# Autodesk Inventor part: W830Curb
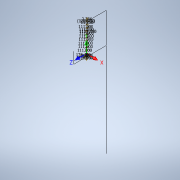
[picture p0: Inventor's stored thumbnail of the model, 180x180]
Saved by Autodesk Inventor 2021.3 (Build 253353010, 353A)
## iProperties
Created: 2021-10
Part Number: W830Curb
Material: Concrete, Cast-in-Place, Gray
Document SubType Name: Modeling
Designer: u1426
Density: 2.40731 g/cm^3
Appearance: Flat - Gray 1
Author: u1426
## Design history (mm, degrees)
node "Annotations"
  node "Linear Dimension 1" dims "d10" = 1016, "d43" = 0, "d130" = 3041.65, "d131" = 54.48719, "d132" = 298.45, "d133" = 298.45, "d134" = 2889.25, "d135" = 54.17486, "d159" = 3340.1 (derived), "d163" = 28752.8, "d164" = 3187.7 (derived), "d165" = 31014.11722 (derived), "d181" = 4431.792, "d182" = 2819.4, "d183" = 2819.4, "d184" = 2819.4, "d185" = 2819.4, "d186" = 2819.4, "d187" = 2819.4, "d188" = 2819.4, "d190" = 2819.4
  node "Linear Dimension 2" dims "d10" = 1016, "d43" = 0, "d130" = 3041.65, "d131" = 54.48719, "d132" = 298.45, "d133" = 298.45, "d134" = 2889.25, "d135" = 54.17486, "d159" = 3340.1 (derived), "d163" = 28752.8, "d164" = 3187.7 (derived), "d170" = 2819.23425 (derived), "d181" = 4431.792, "d182" = 2819.4, "d183" = 2819.4, "d184" = 2819.4, "d185" = 2819.4, "d186" = 2819.4, "d187" = 2819.4, "d188" = 2819.4, "d190" = 2819.4
sketch "Sketch2"
  geometry: L1 (0, -1016)-(-298.45, -1016); L2 (-298.45, -1016)-(-3340.1, -961.513); L3 (28752.8, -1440.402)-(29051.25, -1440.402); L4 (29051.25, -1440.402)-(31940.5, -1494.576); 10 further points
  constraints: 8 end point, 2 horizontal, 12 other
  dimensions: "d10" = 1016 distance of point (0, 0) L1.start; "d43" = 0 horizontal distance of L1.start point (0, 0); "d130" = 3041.65 horizontal distance of L1.end L2.end; "d131" = 54.48719 vertical distance of L1.end L2.end; "d132" = 298.45 distance of L1.start L1.end; "d133" = 298.45 distance of L3.start L3.end; "d134" = 2889.25 horizontal distance of L3.end L4.end; "d135" = 54.17486 vertical distance of L3.end L4.end; "d159" = 3340.1 horizontal distance of L1.start L2.end (derived); "d163" = 28752.8 horizontal distance of L3.start L1.start; "d164" = 3187.7 horizontal distance of L4.end L3.start (derived); "d181" = 4431.792 horizontal distance of point (4431.792, -1089.11) L1.start; "d182" = 2819.4 horizontal distance of point (7251.192, -1134.162) point (4431.792, -1089.11); "d183" = 2819.4 horizontal distance of point (10070.592, -1178.078) point (7251.192, -1134.162); "d184" = 2819.4 horizontal distance of point (12889.992, -1220.86) point (10070.592, -1178.078); "d185" = 2819.4 horizontal distance of point (15709.392, -1262.506) point (12889.992, -1220.86); "d186" = 2819.4 horizontal distance of point (18528.792, -1303.017) point (15709.392, -1262.506); "d187" = 2819.4 horizontal distance of point (21348.192, -1342.393) point (18528.792, -1303.017); "d188" = 2819.4 horizontal distance of point (24167.592, -1380.634) point (21348.192, -1342.393); "d190" = 2819.4 horizontal distance of point (26986.992, -1417.74) point (24167.592, -1380.634)
  node "2D Equation Curve1" dims "d8" = 53060.6, "d9" = 81813.4
workpoint "Work Point1"
pattern_linear "Rectangular Pattern1" dims "d158" = 2133.6
workpoint "Work Point14"
pattern_linear "Rectangular Pattern2" dims "d162" = 2133.6
workpoint "Work Point16"
  workplane "Work Plane1"
sketch "Sketch8"
  geometry: L1 (0, -1038.244)-(-978.62, -1038.244); L2 (-978.62, -1038.244)-(-978.62, -877.156); L3 (-978.62, -877.156)-(0, -877.156); L4 (0, -877.156)-(0, -1038.244); 1 further point
  constraints: 8 end point, 2 parallel, 1 horizontal, 1 perpendicular
extrude "Extrusion5" new body sketch "Sketch8" distance "d193" = 25.4; taper "d194" = 0 deg
feature "Sketch Driven Pattern1"
body "Solid6"
workpoint "Work Point2"
workpoint "Work Point15"
workpoint "Work Point44"
workpoint "Work Point45"
workpoint "Work Point46"
workpoint "Work Point47"
workpoint "Work Point48"
workpoint "Work Point49"
workpoint "Work Point50"
workpoint "Work Point51"
workpoint "Work Point52"
other parameters: "d59" = 12.7, "d63" = 12.7, "d166" = 1612.392, "d172" = 0, "d173" = 0, "d174" = 0, "d175" = 0.1309, "d176" = 0, "d177" = 0
